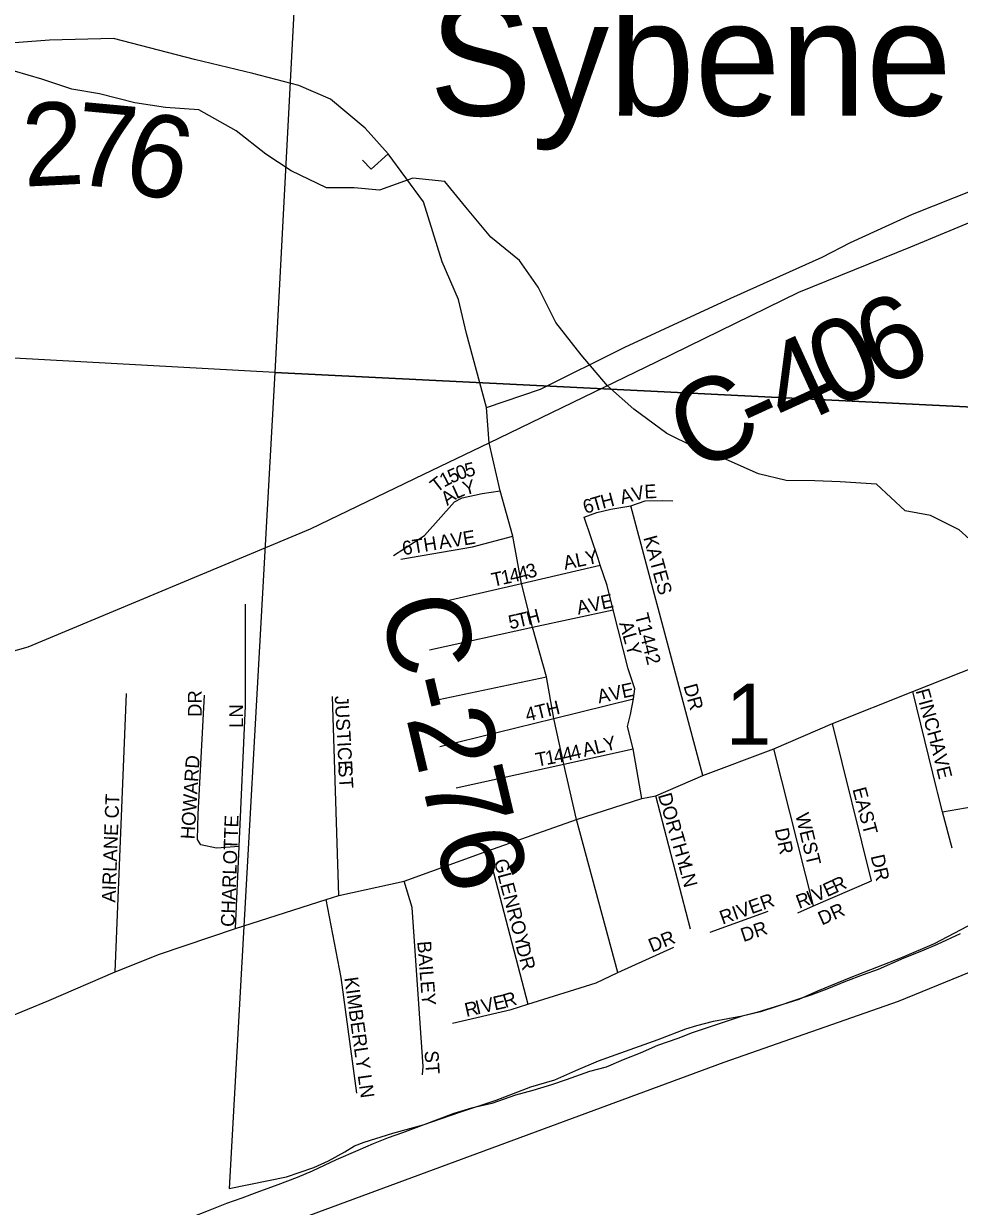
# Model space of a CAD drawing. Extents: x 1949938.81 to 1949945.61, y 152207.65 to 152214.09.
# Drawn here: x 1949944.431 to 1949945.073, y 152208.429 to 152209.24 of the extents above; entities that cross this region are included whole.
import ezdxf

# ---------------------------------------------------------------- set-up
doc = ezdxf.new("R2010")
doc.units = 0
for name, color, linetype in [('GM_X_County', 7, 'Continuous'), ('GM_X_County_Road', 7, 'Continuous'), ('GM_X_County_Road_Text', 7, 'Continuous'), ('GM_X_Major_River', 7, 'Continuous'), ('GM_X_Minor_River', 7, 'Continuous'), ('GM_X_Section', 7, 'Continuous'), ('GM_X_Section_Text', 7, 'Continuous'), ('GM_X_Township', 7, 'Continuous'), ('GM_X_Township_Road', 7, 'Continuous'), ('GM_X_Township_Road_Text', 7, 'Continuous'), ('GM_X_Township_ROW', 7, 'Continuous'), ('GM_X_Township_Subdivision', 7, 'Continuous'), ('GM_X_Township_Subdivision_Text', 7, 'Continuous'), ('GM_X_Unincorporated_Text', 7, 'Continuous'), ('GM_X_US_Route', 7, 'Continuous')]:
    doc.layers.add(name, color=color, linetype=linetype)

msp = doc.modelspace()

# ---------------------------------------------------------------- linework, layer by layer
at = {"layer": 'GM_X_County'}
msp.add_lwpolyline([(1949942.51034, 152208.01072), (1949942.8268, 152208.00464), (1949942.9926, 152208.00728), (1949943.04181, 152208.01904), (1949943.19019, 152208.0433), (1949943.32418, 152208.05808), (1949943.55507, 152208.10092), (1949944.00133, 152208.20671), (1949944.06493, 152208.23174), (1949944.52367, 152208.38458), (1949944.91164, 152208.52796), (1949945.03125, 152208.56968), (1949945.26327, 152208.66452), (1949945.37438, 152208.72503), (1949945.41796, 152208.75242), (1949945.43768, 152208.75815), (1949945.47712, 152208.76732), (1949945.50403, 152208.78255), (1949945.55862, 152208.81147), (1949945.59578, 152208.82368), (1949945.60686, 152208.82659)], dxfattribs=at)
at = {"layer": 'GM_X_County_Road'}
for points in [[(1949944.7487, 152208.97684), (1949944.78583, 152208.98937), (1949944.8436, 152209.01822), (1949944.91631, 152209.05182), (1949944.97891, 152209.07991), (1949944.99822, 152209.09001), (1949945.04072, 152209.1094), (1949945.09823, 152209.13241), (1949945.1345, 152209.14834), (1949945.16547, 152209.16044)], [(1949944.8104, 152208.69434), (1949944.80184, 152208.73227), (1949944.7948, 152208.76365), (1949944.78987, 152208.79205), (1949944.78024, 152208.82622), (1949944.77273, 152208.85625), (1949944.76682, 152208.88853), (1949944.75804, 152208.91974), (1949944.75061, 152208.95264)], [(1949944.41994, 152208.55828), (1949944.44868, 152208.57015), (1949944.49406, 152208.58988), (1949944.52449, 152208.60195), (1949944.57656, 152208.61961), (1949944.63875, 152208.63945), (1949944.64745, 152208.64222), (1949944.69231, 152208.65199), (1949944.74952, 152208.67284), (1949944.8104, 152208.69434), (1949944.85513, 152208.70878), (1949944.86482, 152208.7105), (1949944.89699, 152208.72448), (1949944.94572, 152208.7428), (1949944.98591, 152208.76004), (1949945.041, 152208.78201), (1949945.08486, 152208.79948), (1949945.08816, 152208.80113)]]:
    msp.add_lwpolyline(points, dxfattribs=at)
at = {"layer": 'GM_X_Major_River'}
for points in [[(1949945.07346, 152208.61579), (1949945.05758, 152208.60859), (1949945.04699, 152208.60404), (1949945.03489, 152208.59911), (1949945.01712, 152208.59153), (1949945.0069, 152208.58774), (1949944.9948, 152208.58319), (1949944.98194, 152208.57789), (1949944.97098, 152208.57372), (1949944.96114, 152208.57069), (1949944.94715, 152208.56576), (1949944.93656, 152208.56235), (1949944.92408, 152208.55932), (1949944.91085, 152208.55515), (1949944.90063, 152208.55174), (1949944.88967, 152208.54795), (1949944.87984, 152208.54416), (1949944.86584, 152208.53923), (1949944.85412, 152208.53393), (1949944.84239, 152208.52938), (1949944.83067, 152208.52446), (1949944.81932, 152208.52142), (1949944.80344, 152208.51574), (1949944.79323, 152208.51233), (1949944.78037, 152208.50854), (1949944.76865, 152208.50513), (1949944.75239, 152208.49945), (1949944.73839, 152208.49642), (1949944.72629, 152208.49263), (1949944.71608, 152208.48884), (1949944.70398, 152208.48429), (1949944.69112, 152208.47937), (1949944.68129, 152208.47596), (1949944.67108, 152208.47179), (1949944.66049, 152208.46724), (1949944.64574, 152208.4608), (1949944.6291, 152208.45322), (1949944.61889, 152208.44867)], [(1949944.61889, 152208.44867), (1949944.60565, 152208.44374), (1949944.59128, 152208.43844), (1949944.58107, 152208.43465), (1949944.57048, 152208.43086), (1949944.558, 152208.42593), (1949944.54627, 152208.42138), (1949944.53493, 152208.41722), (1949944.52283, 152208.41305), (1949944.50997, 152208.40774), (1949944.49598, 152208.4013), (1949944.48349, 152208.39372), (1949944.46799, 152208.3869), (1949944.45778, 152208.38197), (1949944.4434, 152208.37439), (1949944.43244, 152208.36984), (1949944.4226, 152208.36491)]]:
    msp.add_lwpolyline(points, dxfattribs=at)
at = {"layer": 'GM_X_Minor_River'}
msp.add_lwpolyline([(1949945.09396, 152208.87382), (1949945.07283, 152208.89288), (1949945.05318, 152208.90282), (1949945.03577, 152208.90592), (1949945.01616, 152208.92422), (1949944.99117, 152208.92583), (1949944.97376, 152208.92666), (1949944.95407, 152208.92673), (1949944.93515, 152208.93136), (1949944.91096, 152208.94208), (1949944.8913, 152208.94974), (1949944.87241, 152208.95893), (1949944.84976, 152208.97572), (1949944.83165, 152208.99173), (1949944.81356, 152209.01306), (1949944.79623, 152209.03515), (1949944.78422, 152209.05949), (1949944.77142, 152209.07777), (1949944.75179, 152209.09379), (1949944.73446, 152209.11436), (1949944.72014, 152209.13188), (1949944.69819, 152209.13424), (1949944.67543, 152209.12598), (1949944.65802, 152209.12756), (1949944.63909, 152209.12763), (1949944.6149, 152209.13912), (1949944.59753, 152209.15057), (1949944.57714, 152209.1666), (1949944.55145, 152209.18113), (1949944.52874, 152209.18273), (1949944.50755, 152209.18585), (1949944.48334, 152209.19202), (1949944.46441, 152209.19513), (1949944.44399, 152209.20204), (1949944.42508, 152209.20743)], dxfattribs=at)
at = {"layer": 'GM_X_Section'}
msp.add_lwpolyline([(1949943.54393, 152210.07541), (1949944.65667, 152210.00648), (1949944.60372, 152209.00094), (1949943.4815, 152209.06269)], close=True, dxfattribs=at)
for points in [[(1949945.60686, 152209.95427), (1949944.65667, 152210.00648), (1949944.60372, 152209.00094), (1949945.60686, 152208.95108)], [(1949945.60686, 152208.95108), (1949944.60372, 152209.00094), (1949944.57229, 152208.44134), (1949944.61169, 152208.44928), (1949944.63026, 152208.4557), (1949944.6405, 152208.46024), (1949944.65149, 152208.4663), (1949944.65831, 152208.47046), (1949944.66476, 152208.47311), (1949944.68446, 152208.47916), (1949944.7053, 152208.48483), (1949944.73032, 152208.49353), (1949944.75533, 152208.50185), (1949944.7792, 152208.51092), (1949944.7955, 152208.51584), (1949944.8099, 152208.52227), (1949944.82544, 152208.5287), (1949944.83756, 152208.53324), (1949944.86637, 152208.54345), (1949944.88532, 152208.55064), (1949944.8929, 152208.55291), (1949944.90427, 152208.55593), (1949944.92397, 152208.5597), (1949944.93496, 152208.56235), (1949944.95202, 152208.56764), (1949944.96301, 152208.57104), (1949944.97589, 152208.57672), (1949944.99863, 152208.58617), (1949945.03388, 152208.59979), (1949945.05586, 152208.60925), (1949945.08769, 152208.6259)]]:
    msp.add_lwpolyline(points, dxfattribs=at)
at = {"layer": 'GM_X_Township'}
msp.add_lwpolyline([(1949942.51034, 152208.01072), (1949942.8268, 152208.00464), (1949942.9926, 152208.00728), (1949943.04181, 152208.01904), (1949943.19019, 152208.0433), (1949943.32418, 152208.05808), (1949943.55507, 152208.10092), (1949944.00133, 152208.20671), (1949944.06493, 152208.23174), (1949944.52367, 152208.38458), (1949944.91164, 152208.52796), (1949945.03125, 152208.56968), (1949945.26327, 152208.66452), (1949945.37438, 152208.72503), (1949945.41796, 152208.75242), (1949945.43768, 152208.75815), (1949945.47712, 152208.76732), (1949945.50403, 152208.78255), (1949945.55862, 152208.81147), (1949945.59578, 152208.82368), (1949945.60686, 152208.82659)], dxfattribs=at)
at = {"layer": 'GM_X_Township_Road'}
for points in [[(1949944.75061, 152208.95264), (1949944.7487, 152208.97684), (1949944.73491, 152209.02757), (1949944.72946, 152209.0509), (1949944.71841, 152209.07668), (1949944.70551, 152209.11784), (1949944.68131, 152209.15084), (1949944.66548, 152209.16845), (1949944.64172, 152209.18825), (1949944.62008, 152209.19782), (1949944.58857, 152209.20594), (1949944.54846, 152209.21553), (1949944.49303, 152209.23005), (1949944.44904, 152209.22873), (1949944.38882, 152209.22429), (1949944.35078, 152209.2338), (1949944.31403, 152209.23944)], [(1949944.83876, 152208.58927), (1949944.8104, 152208.69434)]]:
    msp.add_lwpolyline(points, dxfattribs=at)
at = {"layer": 'GM_X_Township_ROW'}
for points in [[(1949944.82518, 152208.87326), (1949944.81577, 152208.90167)], [(1949944.58356, 152208.77215), (1949944.58356, 152208.84202)], [(1949944.71165, 152208.77562), (1949944.78987, 152208.79205)], [(1949944.85513, 152208.70878), (1949944.84919, 152208.74272), (1949944.84535, 152208.75809), (1949944.84739, 152208.76631), (1949944.84957, 152208.77714)], [(1949945.06801, 152208.67461), (1949945.06142, 152208.69965), (1949945.0579, 152208.71304), (1949945.05747, 152208.71478)]]:
    msp.add_lwpolyline(points, dxfattribs=at)
at = {"layer": 'GM_X_Township_Subdivision'}
for points in [[(1949944.66364, 152209.14646), (1949944.66966, 152209.14043), (1949944.68131, 152209.15084)], [(1949944.68506, 152208.87536), (1949944.70619, 152208.88908), (1949944.72676, 152208.91214), (1949944.73197, 152208.91488), (1949944.74569, 152208.9179), (1949944.75804, 152208.91974)], [(1949944.81577, 152208.90167), (1949944.82436, 152208.9048), (1949944.83395, 152208.90714), (1949944.84776, 152208.9094), (1949944.85742, 152208.9128), (1949944.86967, 152208.91308), (1949944.87652, 152208.9128)], [(1949944.89699, 152208.72448), (1949944.84776, 152208.9094)], [(1949944.68995, 152208.87293), (1949944.73907, 152208.88142), (1949944.76682, 152208.88853)], [(1949944.71006, 152208.84181), (1949944.77273, 152208.85625), (1949944.82669, 152208.86868)], [(1949944.84957, 152208.77714), (1949944.84957, 152208.77715), (1949944.85036, 152208.78403), (1949944.84573, 152208.79761), (1949944.83544, 152208.83819), (1949944.83147, 152208.8549), (1949944.82669, 152208.86868), (1949944.82518, 152208.87326)], [(1949944.70955, 152208.81062), (1949944.78024, 152208.82622), (1949944.83544, 152208.83819)], [(1949944.49406, 152208.58988), (1949944.50193, 152208.78066)], [(1949944.57913, 152208.67577), (1949944.56362, 152208.67465), (1949944.55294, 152208.67703), (1949944.55057, 152208.68059), (1949944.55097, 152208.69799), (1949944.55532, 152208.77947)], [(1949944.64745, 152208.64222), (1949944.6431, 152208.77868)], [(1949945.05747, 152208.71478), (1949945.041, 152208.78201)], [(1949944.57656, 152208.61961), (1949944.57913, 152208.67577), (1949944.58356, 152208.77215)], [(1949944.7168, 152208.74443), (1949944.7948, 152208.76365), (1949944.84957, 152208.77715)], [(1949945.01259, 152208.65233), (1949944.98591, 152208.76004)], [(1949944.72792, 152208.71598), (1949944.80184, 152208.73227), (1949944.84919, 152208.74272)], [(1949944.97295, 152208.63499), (1949944.94572, 152208.7428)], [(1949944.8886, 152208.61919), (1949944.86482, 152208.7105)], [(1949945.06142, 152208.69965), (1949945.08226, 152208.70332)], [(1949944.74952, 152208.67284), (1949944.77708, 152208.56763)], [(1949944.70494, 152208.51928), (1949944.70532, 152208.52497), (1949944.69767, 152208.63391), (1949944.69231, 152208.65199)], [(1949944.96225, 152208.6303), (1949944.97295, 152208.63499), (1949945.01259, 152208.65233)], [(1949944.65973, 152208.50668), (1949944.64903, 152208.58605), (1949944.63875, 152208.63945)], [(1949944.90202, 152208.61709), (1949944.9418, 152208.63135)], [(1949944.72546, 152208.55451), (1949944.76555, 152208.56399), (1949944.77708, 152208.56763), (1949944.82379, 152208.5822), (1949944.83876, 152208.58927), (1949944.87712, 152208.60685)]]:
    msp.add_lwpolyline(points, dxfattribs=at)
at = {"layer": 'GM_X_US_Route'}
for points in [[(1949944.70565, 152208.93105), (1949944.75061, 152208.95264), (1949944.86523, 152209.00809), (1949944.96279, 152209.05596), (1949945.03968, 152209.08715), (1949945.1044, 152209.114), (1949945.16887, 152209.13464), (1949945.24969, 152209.15953), (1949945.30962, 152209.17864), (1949945.37874, 152209.19813), (1949945.56792, 152209.26041), (1949945.60686, 152209.27505)], [(1949942.76767, 152208.37641), (1949942.87003, 152208.40953), (1949943.18792, 152208.50728), (1949943.33467, 152208.55006), (1949943.55269, 152208.60395), (1949943.67422, 152208.6353), (1949943.838, 152208.67152), (1949944.0262, 152208.71377), (1949944.17953, 152208.74974), (1949944.26416, 152208.7689), (1949944.2681, 152208.76979), (1949944.36443, 152208.79307), (1949944.43457, 152208.8128), (1949944.62799, 152208.89375), (1949944.70565, 152208.93105)]]:
    msp.add_lwpolyline(points, dxfattribs=at)

# ---------------------------------------------------------------- texts
at = {"layer": 'GM_X_County_Road_Text'}
for s, height, rotation, p in [('6', 0.05682, 23.96103, (1949945.01773, 152208.9897)), ('0', 0.05682, 24.48874, (1949944.986, 152208.97525)), ('4', 0.05682, 24.57911, (1949944.9542, 152208.9607)), ('C', 0.05682, 24.61321, (1949944.89057, 152208.93155)), ('-', 0.05682, 24.60878, (1949944.93299, 152208.95099)), ('C-276', 0.056818, 283.3713, (1949944.67499, 152208.84219))]:
    msp.add_text(s, height=height, rotation=rotation, dxfattribs=at).set_placement(p)
at = {"layer": 'GM_X_Section_Text'}
msp.add_text('1', height=0.04186, rotation=0.00001, dxfattribs=at).set_placement((1949944.91279, 152208.74553))
at = {"layer": 'GM_X_Township_Road_Text'}
for s, rotation, p in [('2', 2.83622, (1949944.43167, 152209.12829)), ('7', 354.6594, (1949944.46449, 152209.13006)), ('6', 345.68261, (1949944.49702, 152209.12721))]:
    msp.add_text(s, height=0.05682, rotation=rotation, dxfattribs=at).set_placement(p)
at = {"layer": 'GM_X_Township_Subdivision_Text'}
for s, height, rotation, p in [('1', 0.00947, 27.87779, (1949944.71963, 152208.92194)), ('5', 0.00947, 23.65083, (1949944.72462, 152208.92459)), ('0', 0.00947, 21.34913, (1949944.72987, 152208.92689)), ('5', 0.00947, 12.75272, (1949944.73495, 152208.9289)), ('T', 0.00947, 38.01757, (1949944.71475, 152208.91807)), ('Y', 0.00947, 14.39011, (1949944.73373, 152208.91654)), ('V', 0.00947, 12.63667, (1949944.84948, 152208.91259)), ('E', 0.00947, 3.23381, (1949944.8572, 152208.91436)), ('A', 0.00947, 36.61525, (1949944.72184, 152208.90924)), ('L', 0.00947, 24.31308, (1949944.72806, 152208.91394)), ('T', 0.00947, 16.46731, (1949944.82203, 152208.90549)), ('H', 0.00947, 14.74398, (1949944.82835, 152208.90736)), ('A', 0.00947, 14.4842, (1949944.84149, 152208.91052)), ('6', 0.00947, 16.46188, (1949944.81643, 152208.90384)), ('V', 0.00947, 8.56616, (1949944.72494, 152208.88098)), ('E', 0.00947, 9.51706, (1949944.73335, 152208.88224)), ('6TH', 0.00947, 9.08962, (1949944.69167, 152208.87556)), ('A', 0.00947, 8.56616, (1949944.7167, 152208.87973)), ('KATES', 0.00947, 285.25642, (1949944.85617, 152208.88761)), ('ALY', 0.00947, 11.68971, (1949944.80243, 152208.86552)), ('4', 0.00947, 12.80532, (1949944.76555, 152208.85654)), ('4', 0.00947, 14.81731, (1949944.77159, 152208.85792)), ('3', 0.00947, 15.85081, (1949944.77741, 152208.85946)), ('T', 0.00947, 12.3199, (1949944.75325, 152208.85385)), ('1', 0.00947, 12.32511, (1949944.75976, 152208.85528)), ('AVE', 0.00947, 12.09489, (1949944.81158, 152208.83471)), ('5', 0.00947, 12.75748, (1949944.76491, 152208.82471)), ('T', 0.00947, 12.76374, (1949944.77061, 152208.826)), ('H', 0.00947, 14.55524, (1949944.77742, 152208.82755)), ('T1442', 0.00947, 284.42487, (1949944.85031, 152208.83443)), ('ALY', 0.00947, 285.95152, (1949944.83957, 152208.82884)), ('AVE', 0.00947, 12.09489, (1949944.82575, 152208.77388)), ('DR', 0.00947, 285.516, (1949944.88367, 152208.78595)), ('DR', 0.00947, 90, (1949944.55351, 152208.76464)), ('JUSTICE', 0.00947, 273.24204, (1949944.64457, 152208.77891)), ('FINCH', 0.00947, 285.37839, (1949945.04284, 152208.78261)), ('LN', 0.00947, 90, (1949944.58184, 152208.75714)), ('4TH', 0.00947, 13.49655, (1949944.77655, 152208.76137)), ('4', 0.00947, 13.52227, (1949944.80757, 152208.73524)), ('A', 0.00947, 13.73764, (1949944.8157, 152208.73721)), ('L', 0.00947, 13.73711, (1949944.8238, 152208.73919)), ('Y', 0.00947, 13.73634, (1949944.83027, 152208.74077)), ('AVE', 0.00947, 284.03613, (1949945.05285, 152208.7459)), ('HOWARD', 0.00947, 86.36561, (1949944.5485, 152208.68052)), ('T', 0.00947, 10.5626, (1949944.78334, 152208.73044)), ('1', 0.00947, 10.56595, (1949944.78989, 152208.73167)), ('4', 0.00947, 10.56499, (1949944.79563, 152208.73273)), ('4', 0.00947, 13.17593, (1949944.80182, 152208.7339)), ('ST', 0.00947, 273.57438, (1949944.64707, 152208.73142)), ('EAST', 0.00947, 284.82469, (1949944.99951, 152208.71509)), ('AIRLANE CT', 0.00947, 87.90323, (1949944.49434, 152208.6372)), ('DORTHY', 0.00947, 286.2191, (1949944.86616, 152208.71097)), ('CHARLOTTE', 0.00947, 87.95365, (1949944.57601, 152208.62051)), ('WEST', 0.00947, 283.66969, (1949944.96035, 152208.69756)), ('DR', 0.00947, 281.89338, (1949944.94626, 152208.68752)), ('GLENROY', 0.00947, 284.87745, (1949944.75368, 152208.66593)), ('DR', 0.00947, 282.53371, (1949945.01202, 152208.66919)), ('LN', 0.00947, 284.74654, (1949944.88034, 152208.66259)), ('V', 0.00947, 24.61184, (1949944.97459, 152208.63749)), ('E', 0.00947, 24.89648, (1949944.98222, 152208.64098)), ('R', 0.00947, 24.89819, (1949944.98826, 152208.64378)), ('RIVER', 0.00947, 19.74801, (1949944.91052, 152208.62215)), ('R', 0.00947, 20.44023, (1949944.96303, 152208.63298)), ('I', 0.00947, 22.57572, (1949944.97041, 152208.63574)), ('DR', 0.00947, 23.96069, (1949944.97861, 152208.62154)), ('DR', 0.00947, 18.43324, (1949944.92482, 152208.61021)), ('DR', 0.00947, 22.37789, (1949944.86211, 152208.60295)), ('BAILEY', 0.00947, 274.48642, (1949944.70123, 152208.61061)), ('DR', 0.00947, 285.52727, (1949944.76867, 152208.60761)), ('KIMBERLY LN', 0.0094697, 277.87196, (1949944.65118, 152208.58571)), ('R', 0.00947, 16.40478, (1949944.76153, 152208.56496)), ('R', 0.00947, 12.83145, (1949944.73491, 152208.55888)), ('I', 0.00947, 12.82618, (1949944.74223, 152208.56054)), ('V', 0.00947, 12.82885, (1949944.74629, 152208.56147)), ('E', 0.00947, 12.82863, (1949944.75441, 152208.56332)), ('ST', 0.00947, 273.5744, (1949944.70623, 152208.53558))]:
    msp.add_text(s, height=height, rotation=rotation, dxfattribs=at).set_placement(p)
at = {"layer": 'GM_X_Unincorporated_Text'}
msp.add_text('Sybene', height=0.078977, rotation=0.00001, dxfattribs=at).set_placement((1949944.70945, 152209.17709))

doc.saveas('drawing.dxf')
